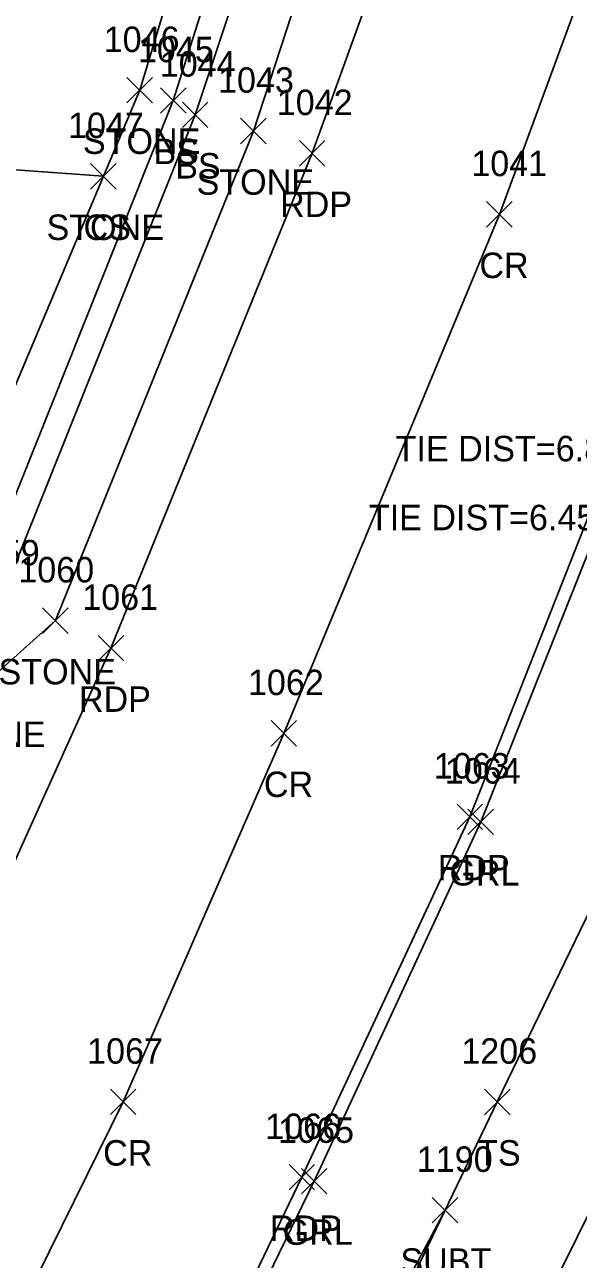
# Model space of a CAD drawing. Extents: x 1599840 to 1601211, y 518904 to 521989.
# Drawn here: x 1600880.7 to 1600924.1, y 521353.5 to 521450.4 of the extents above; entities that cross this region are included whole.
import ezdxf

# ---------------------------------------------------------------- set-up
doc = ezdxf.new("R2010")
doc.units = 0
for name, color, linetype in [('C_C', 7, 'Continuous'), ('L_A', 7, 'Continuous'), ('L_I', 7, 'Continuous'), ('L_TIC', 7, 'Continuous'), ('LASF', 7, 'Continuous'), ('LELB', 7, 'Continuous'), ('P_A', 7, 'Continuous'), ('P_I', 7, 'Continuous'), ('P_TIC', 7, 'Continuous'), ('PET', 7, 'Continuous'), ('PRC', 7, 'Continuous'), ('R_A', 7, 'Continuous'), ('R_I', 7, 'Continuous'), ('R_TIC', 7, 'Continuous'), ('RGR', 7, 'Continuous'), ('U_A', 7, 'Continuous'), ('U_I', 7, 'Continuous'), ('U_TIC', 7, 'Continuous'), ('UT', 7, 'Continuous')]:
    doc.layers.add(name, color=color, linetype=linetype)

msp = doc.modelspace()

# ---------------------------------------------------------------- linework, layer by layer
at = {"layer": 'L_TIC'}
for points in [[(1600888.738, 521444.235), (1600890.738, 521446.235)], [(1600890.738, 521444.235), (1600888.738, 521446.235)], [(1600891.372, 521443.434), (1600893.372, 521445.434)], [(1600893.372, 521443.434), (1600891.372, 521445.434)], [(1600893.081, 521442.303), (1600895.081, 521444.303)], [(1600895.081, 521442.303), (1600893.081, 521444.303)], [(1600897.654, 521441.034), (1600899.654, 521443.034)], [(1600899.654, 521441.034), (1600897.654, 521443.034)], [(1600885.885, 521437.481), (1600887.885, 521439.481)], [(1600887.885, 521437.481), (1600885.885, 521439.481)], [(1600885.885, 521437.481), (1600887.885, 521439.481)], [(1600887.885, 521437.481), (1600885.885, 521439.481)], [(1600882.119, 521402.602), (1600884.119, 521404.602)], [(1600884.119, 521402.602), (1600882.119, 521404.602)], [(1600916.789, 521364.826), (1600918.789, 521366.826)], [(1600918.789, 521364.826), (1600916.789, 521366.826)]]:
    msp.add_lwpolyline(points, dxfattribs=at)
at = {"layer": 'LASF'}
for points in [[(1600911.546, 521511.932), (1600900.224, 521479.947), (1600889.738, 521445.235), (1600886.885, 521438.481), (1600872.337, 521439.531), (1600863.462, 521422.268), (1600865.406, 521415.757), (1600864.458, 521412.26), (1600859.405, 521407.599), (1600852.703, 521401.768), (1600833.295, 521392.861), (1600833.786, 521390.599)], [(1600919.139, 521509.382), (1600909.758, 521476.008), (1600898.654, 521442.034), (1600883.119, 521403.602), (1600877.594, 521398.681), (1600871.885, 521396.639), (1600869.037, 521399.635), (1600868.644, 521401.061), (1600852.114, 521396.92), (1600833.786, 521390.599)]]:
    msp.add_lwpolyline(points, dxfattribs=at)
at = {"layer": 'LELB'}
for points in [[(1600913.3, 521511.459), (1600903.304, 521478.92), (1600892.372, 521444.434), (1600876.873, 521405.745), (1600868.644, 521401.061)], [(1600915.473, 521510.949), (1600905.575, 521477.831), (1600894.081, 521443.303), (1600878.723, 521404.941), (1600869.037, 521399.635), (1600852.727, 521394.053), (1600835.193, 521387.311), (1600828.421, 521384.037)], [(1600966.092, 521495.518), (1600959.783, 521473.277), (1600948.847, 521440.966), (1600941.086, 521418.297), (1600930.043, 521391.16), (1600917.789, 521365.826), (1600907.009, 521343.383), (1600893.447, 521320.991), (1600884.033, 521297.589), (1600887.61, 521294.187)], [(1600886.885, 521438.481), (1600874.623, 521409.419), (1600872.546, 521405.524)], [(1600939.057, 521387.921), (1600926.772, 521360.698), (1600917.248, 521341.477)]]:
    msp.add_lwpolyline(points, dxfattribs=at)
at = {"layer": 'P_TIC'}
for points in [[(1600902.262, 521439.284), (1600904.262, 521441.284)], [(1600904.262, 521439.284), (1600902.262, 521441.284)], [(1600916.952, 521434.491), (1600918.952, 521436.491)], [(1600918.952, 521434.491), (1600916.952, 521436.491)], [(1600886.481, 521400.444), (1600888.481, 521402.444)], [(1600888.481, 521400.444), (1600886.481, 521402.444)], [(1600900.045, 521393.756), (1600902.045, 521395.756)], [(1600902.045, 521393.756), (1600900.045, 521395.756)], [(1600914.63, 521387.211), (1600916.63, 521389.211)], [(1600916.63, 521387.211), (1600914.63, 521389.211)], [(1600887.433, 521364.829), (1600889.433, 521366.829)], [(1600889.433, 521364.829), (1600887.433, 521366.829)], [(1600901.456, 521358.916), (1600903.456, 521360.916)], [(1600903.456, 521358.916), (1600901.456, 521360.916)]]:
    msp.add_lwpolyline(points, dxfattribs=at)
at = {"layer": 'PET'}
for points in [[(1600925.829, 521507.518), (1600915.18, 521473.309), (1600903.262, 521440.284), (1600887.481, 521401.444), (1600873.353, 521370.155), (1600860.378, 521343.642), (1600847.931, 521319.686), (1600844.651, 521313.138), (1600836.724, 521299.896), (1600818.79, 521271.507), (1600793.687, 521233.92), (1600774.487, 521208.057), (1600757.089, 521185.54), (1600730.915, 521154.494)], [(1600955.79, 521499.343), (1600943.511, 521460.897), (1600932.487, 521430.948), (1600915.63, 521388.211), (1600902.456, 521359.916), (1600888.209, 521330.269), (1600876.228, 521308.06), (1600874.776, 521305.59), (1600851.304, 521265.606), (1600837.438, 521243.854), (1600825.081, 521225.622), (1600799.946, 521190.819), (1600794.125, 521183.147), (1600773.798, 521157.792), (1600751.791, 521131.813)]]:
    msp.add_lwpolyline(points, dxfattribs=at)
at = {"layer": 'PRC'}
msp.add_lwpolyline([(1600941.106, 521503.298), (1600929.217, 521466.102), (1600917.952, 521435.491), (1600901.045, 521394.756), (1600888.433, 521365.829), (1600873.974, 521336.548), (1600862.777, 521315.405), (1600848.879, 521291.082), (1600831.543, 521262.943), (1600805.415, 521224.439), (1600786.953, 521198.806), (1600768.666, 521175.321), (1600742.32, 521144.023)], dxfattribs=at)
at = {"layer": 'R_TIC'}
for points in [[(1600915.489, 521386.814), (1600917.489, 521388.814)], [(1600917.489, 521386.814), (1600915.489, 521388.814)], [(1600902.417, 521358.612), (1600904.417, 521360.612)], [(1600904.417, 521358.612), (1600902.417, 521360.612)]]:
    msp.add_lwpolyline(points, dxfattribs=at)
at = {"layer": 'RGR'}
msp.add_lwpolyline([(1600956.838, 521499.158), (1600944.348, 521460.546), (1600933.482, 521430.454), (1600916.489, 521387.814), (1600903.417, 521359.612), (1600888.961, 521329.845), (1600882.66, 521317.566), (1600880.822, 521311.636), (1600881.592, 521304.978)], dxfattribs=at)
at = {"layer": 'U_TIC'}
for points in [[(1600912.689, 521356.335), (1600914.689, 521358.335)], [(1600914.689, 521356.335), (1600912.689, 521358.335)]]:
    msp.add_lwpolyline(points, dxfattribs=at)
at = {"layer": 'UT'}
msp.add_lwpolyline([(1600881.576, 521295.485), (1600899.969, 521331.58), (1600913.689, 521357.335)], dxfattribs=at)

# ---------------------------------------------------------------- texts
at = {"layer": 'C_C'}
for s, p in [('TIE DIST=6.87 TOP CORNER OF', (1600909.814, 521416.108)), ('TIE DIST=6.45 TOP CORNER OF', (1600907.715, 521410.698))]:
    msp.add_text(s, height=2, dxfattribs=at).set_placement(p)
at = {"layer": 'L_A'}
for s, p in [('STONE', (1600885.281, 521440.235)), ('BS', (1600890.813, 521439.434)), ('BS', (1600892.522, 521438.303)), ('STONE', (1600894.198, 521437.034)), ('STONE', (1600882.429, 521433.481)), ('CS', (1600885.326, 521433.481)), ('STONE', (1600878.662, 521398.602)), ('STONE', (1600873.138, 521393.681)), ('TS', (1600916.199, 521360.826))]:
    msp.add_text(s, height=2, dxfattribs=at).set_placement(p)
at = {"layer": 'L_I'}
for s, p in [('1046', (1600886.911, 521448.235)), ('1045', (1600889.601, 521447.434)), ('1044', (1600891.31, 521446.303)), ('1043', (1600895.883, 521445.034)), ('1047', (1600884.114, 521441.481)), ('1047', (1600884.114, 521441.481)), ('1059', (1600875.944, 521407.941)), ('1060', (1600880.213, 521406.602)), ('1206', (1600914.963, 521368.826))]:
    msp.add_text(s, height=2, dxfattribs=at).set_placement(p)
at = {"layer": 'P_A'}
for s, p in [('RDP', (1600900.75, 521435.284)), ('CR', (1600916.385, 521430.491)), ('RDP', (1600884.969, 521396.444)), ('CR', (1600899.478, 521389.756)), ('RDP', (1600913.118, 521383.211)), ('CR', (1600886.866, 521360.829)), ('RDP', (1600899.944, 521354.916))]:
    msp.add_text(s, height=2, dxfattribs=at).set_placement(p)
at = {"layer": 'P_I'}
for s, p in [('1042', (1600900.49, 521443.284)), ('1041', (1600915.747, 521438.491)), ('1061', (1600885.229, 521404.444)), ('1062', (1600898.227, 521397.756)), ('1063', (1600912.812, 521391.211)), ('1067', (1600885.614, 521368.829)), ('1066', (1600899.582, 521362.916))]:
    msp.add_text(s, height=2, dxfattribs=at).set_placement(p)
at = {"layer": 'R_A'}
for p in [(1600914.033, 521382.814), (1600900.96, 521354.612)]:
    msp.add_text('GRL', height=2, dxfattribs=at).set_placement(p)
at = {"layer": 'R_I'}
for s, p in [('1064', (1600913.671, 521390.814)), ('1065', (1600900.598, 521362.612))]:
    msp.add_text(s, height=2, dxfattribs=at).set_placement(p)
at = {"layer": 'U_A'}
msp.add_text('SUBT', height=2, dxfattribs=at).set_placement((1600910.185, 521352.335))
at = {"layer": 'U_I'}
msp.add_text('1190', height=2, dxfattribs=at).set_placement((1600911.477, 521360.335))

doc.saveas('drawing.dxf')
